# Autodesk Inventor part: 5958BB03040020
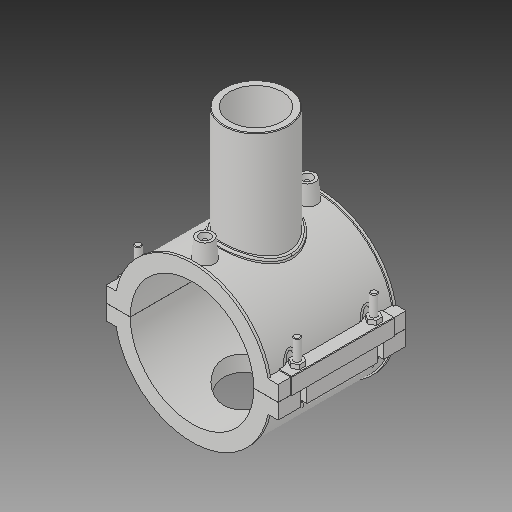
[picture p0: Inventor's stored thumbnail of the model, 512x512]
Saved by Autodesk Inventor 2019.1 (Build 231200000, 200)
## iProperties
Created: 2017-07
Part Number: 5958BB03040020
Material: Generic
Description: PLASSON BRANCH SADDLE 4'' x 2''
Document SubType Name: Modeling
Designer: KIM
Mass: 764.267 g
Surface Area: 1930.38 cm^2
Volume: 764.267 cm^3
Density: 1 g/cm^3
Appearance: Default
Author: KIM
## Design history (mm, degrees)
derived "5958B.ipt"
feature "Solid1::5958B.ipt"
feature "Solid2::5958B.ipt"
feature "Solid3::5958B.ipt"
tag "TaggingFeature1"
body "Solid1"
body "Solid2"
body "Solid3"
other parameters: "d_" = 114.1, "B_" = 159.004, "H_" = 97.028, "L_" = 118.11, "d_t" = 6, "d_1" = 60.1, "H_1" = 83.82, "d1" = 140.516, "d148" = 2.8525, "d160" = 2.8525, "d0" = 114.1, "d2" = 159.004, "d3" = 28.525, "d4" = 118.11, "d5" = 0, "d6" = 0.1, "d8" = 0, "d19" = 6, "d20" = 6, "d21" = 70.866, "d23" = 0, "d24" = 35.433, "d26" = 0, "d27" = 3, "d28" = 3, "d29" = 3, "d30" = 38.03333, "d31" = 6, "d32" = 0, "d33" = 0, "d34" = 0.6, "d40" = 73.06832, "d41" = 66.11, "d43" = 0, "d45" = 0, "d47" = 167.286, "d48" = 60.1, "d50" = 0, "d70" = 15, "d72" = 0, "d73" = 6, "d75" = 5, "d76" = 0, "d77" = 5.705, "d78" = 87.05, "d79" = 15, "d80" = 47.244, "d82" = 5 deg, "d84" = 4, "d85" = 14, "d86" = 0, "d87" = 3, "d88" = 0, "d89" = 1, "d90" = 1, "d91" = 94.488, "d92" = 0, "d93" = 0.5, "d94" = 60.05263, "d96" = 143.32632, "d97" = 2.3622, "d98" = 0, "d102" = 1.803, "d103" = 48.08, "d105" = 0, "d109" = -32.34267, "d117" = 0.601, "d120" = 140 deg, "d121" = 24.228, "d122" = 20 deg, "d123" = 281.032, "d124" = 84.3096, "d126" = 0, "d143" = 119.805, "d150" = 20.538, "d159" = 5.2832, "d161" = 2.8525, "d162" = 70.866, "d163" = 0, "d167" = 22.82, "d168" = 63.87091, "d173" = 1, "d175" = 57.05, "d176" = 20 deg, "d177" = 7.987, "d178" = 26.416, "d180" = 0, "d185" = 38.38575, "d186" = 38.38575, "d187" = 70.258, "d188" = 7.9248, "d189" = 7.987, "d190" = 0, "d191" = 105.387, "d200" = 13.208, "d202" = 0, "d216" = 106.299, "d217" = 0, "d221" = 43.7007, "d222" = 7.987, "d223" = 4.7922, "d224" = 57.05, "d225" = 4.7922, "d227" = 16.4304, "d230" = 70.742, "d236" = 11.5 deg, "d238" = 20 deg, "d239" = 7.987, "d240" = 0, "d241" = 0, "d242" = 6.2484
